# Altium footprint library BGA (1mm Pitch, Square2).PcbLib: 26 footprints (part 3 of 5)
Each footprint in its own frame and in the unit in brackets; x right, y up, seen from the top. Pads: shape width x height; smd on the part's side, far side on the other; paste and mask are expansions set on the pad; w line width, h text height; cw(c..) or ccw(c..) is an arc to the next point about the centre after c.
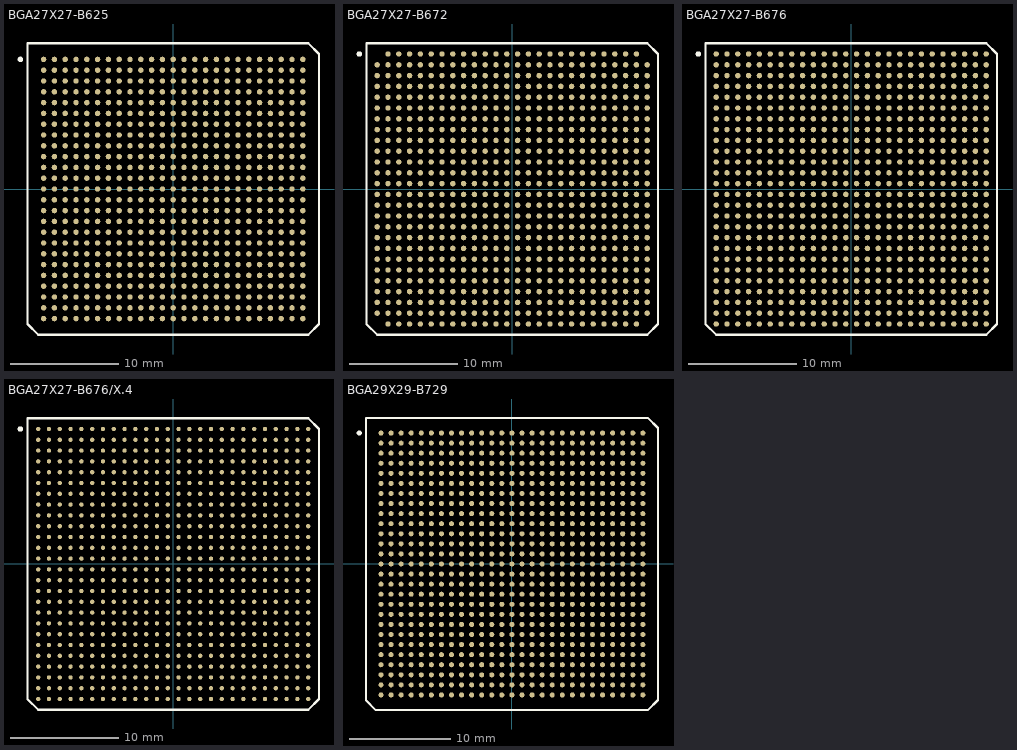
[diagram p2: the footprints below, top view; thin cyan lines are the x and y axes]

## BGA27X27-B625 [mm]
pads (625):
  round 0.5 smd: A1(-12,12) A2(-11,12) A3(-10,12) A4(-9,12) A5(-8,12) A6(-7,12) A7(-6,12) A8(-5,12) A9(-4,12) A10(-3,12) A11(-2,12) A12(-1,12) A13(0,12) A14(1,12) A15(2,12) A16(3,12) A17(4,12) A18(5,12) A19(6,12) A20(7,12) A21(8,12) A22(9,12) A23(10,12) A24(11,12) A25(12,12) AA1(-12,-8) AA2(-11,-8) AA3(-10,-8) AA4(-9,-8) AA5(-8,-8) AA6(-7,-8) AA7(-6,-8) AA8(-5,-8) AA9(-4,-8) AA10(-3,-8) AA11(-2,-8) AA12(-1,-8) AA13(0,-8) AA14(1,-8) AA15(2,-8) AA16(3,-8) AA17(4,-8) AA18(5,-8) AA19(6,-8) AA20(7,-8) AA21(8,-8) AA22(9,-8) AA23(10,-8) AA24(11,-8) AA25(12,-8) AB1(-12,-9) AB2(-11,-9) AB3(-10,-9) AB4(-9,-9) AB5(-8,-9) AB6(-7,-9) AB7(-6,-9) AB8(-5,-9) AB9(-4,-9) AB10(-3,-9) AB11(-2,-9) AB12(-1,-9) AB13(0,-9) AB14(1,-9) AB15(2,-9) AB16(3,-9) AB17(4,-9) AB18(5,-9) AB19(6,-9) AB20(7,-9) AB21(8,-9) AB22(9,-9) AB23(10,-9) AB24(11,-9) AB25(12,-9) AC1(-12,-10) AC2(-11,-10) AC3(-10,-10) AC4(-9,-10) AC5(-8,-10) AC6(-7,-10) AC7(-6,-10) AC8(-5,-10) AC9(-4,-10) AC10(-3,-10) AC11(-2,-10) AC12(-1,-10) AC13(0,-10) AC14(1,-10) AC15(2,-10) AC16(3,-10) AC17(4,-10) AC18(5,-10) AC19(6,-10) AC20(7,-10) AC21(8,-10) AC22(9,-10) AC23(10,-10) AC24(11,-10) AC25(12,-10) AD1(-12,-11) AD2(-11,-11) AD3(-10,-11) AD4(-9,-11) AD5(-8,-11) AD6(-7,-11) AD7(-6,-11) AD8(-5,-11) AD9(-4,-11) AD10(-3,-11) AD11(-2,-11) AD12(-1,-11) AD13(0,-11) AD14(1,-11) AD15(2,-11) AD16(3,-11) AD17(4,-11) AD18(5,-11) AD19(6,-11) AD20(7,-11) AD21(8,-11) AD22(9,-11) AD23(10,-11) AD24(11,-11) AD25(12,-11) AE1(-12,-12) AE2(-11,-12) AE3(-10,-12) AE4(-9,-12) AE5(-8,-12) AE6(-7,-12) AE7(-6,-12) AE8(-5,-12) AE9(-4,-12) AE10(-3,-12) AE11(-2,-12) AE12(-1,-12) AE13(0,-12) AE14(1,-12) AE15(2,-12) AE16(3,-12) AE17(4,-12) AE18(5,-12) AE19(6,-12) AE20(7,-12) AE21(8,-12) AE22(9,-12) AE23(10,-12) AE24(11,-12) AE25(12,-12) B1(-12,11) B2(-11,11) B3(-10,11) B4(-9,11) B5(-8,11) B6(-7,11) B7(-6,11) B8(-5,11) B9(-4,11) B10(-3,11) B11(-2,11) B12(-1,11) B13(0,11) B14(1,11) B15(2,11) B16(3,11) B17(4,11) B18(5,11) B19(6,11) B20(7,11) B21(8,11) B22(9,11) B23(10,11) B24(11,11) B25(12,11) C1(-12,10) C2(-11,10) C3(-10,10) C4(-9,10) C5(-8,10) C6(-7,10) C7(-6,10) C8(-5,10) C9(-4,10) C10(-3,10) C11(-2,10) C12(-1,10) C13(0,10) C14(1,10) C15(2,10) C16(3,10) C17(4,10) C18(5,10) C19(6,10) C20(7,10) C21(8,10) C22(9,10) C23(10,10) C24(11,10) C25(12,10) D1(-12,9) D2(-11,9) D3(-10,9) D4(-9,9) D5(-8,9) D6(-7,9) D7(-6,9) D8(-5,9) D9(-4,9) D10(-3,9) D11(-2,9) D12(-1,9) D13(0,9) D14(1,9) D15(2,9) D16(3,9) D17(4,9) D18(5,9) D19(6,9) D20(7,9) D21(8,9) D22(9,9) D23(10,9) D24(11,9) D25(12,9) E1(-12,8) E2(-11,8) E3(-10,8) E4(-9,8) E5(-8,8) E6(-7,8) E7(-6,8) E8(-5,8) E9(-4,8) E10(-3,8) E11(-2,8) E12(-1,8) E13(0,8) E14(1,8) E15(2,8) E16(3,8) E17(4,8) E18(5,8) E19(6,8) E20(7,8) E21(8,8) E22(9,8) E23(10,8) E24(11,8) E25(12,8) F1(-12,7) F2(-11,7) F3(-10,7) F4(-9,7) F5(-8,7) F6(-7,7) F7(-6,7) F8(-5,7) F9(-4,7) F10(-3,7) F11(-2,7) F12(-1,7) F13(0,7) F14(1,7) F15(2,7) F16(3,7) F17(4,7) F18(5,7) F19(6,7) F20(7,7) F21(8,7) F22(9,7) F23(10,7) F24(11,7) F25(12,7) G1(-12,6) G2(-11,6) G3(-10,6) G4(-9,6) G5(-8,6) G6(-7,6) G7(-6,6) G8(-5,6) G9(-4,6) G10(-3,6) G11(-2,6) G12(-1,6) G13(0,6) G14(1,6) G15(2,6) G16(3,6) G17(4,6) G18(5,6) G19(6,6) G20(7,6) G21(8,6) G22(9,6) G23(10,6) G24(11,6) G25(12,6) H1(-12,5) H2(-11,5) H3(-10,5) H4(-9,5) H5(-8,5) H6(-7,5) H7(-6,5) H8(-5,5) H9(-4,5) H10(-3,5) H11(-2,5) H12(-1,5) H13(0,5) H14(1,5) H15(2,5) H16(3,5) H17(4,5) H18(5,5) H19(6,5) H20(7,5) H21(8,5) H22(9,5) H23(10,5) H24(11,5) H25(12,5) J1(-12,4) J2(-11,4) J3(-10,4) J4(-9,4) J5(-8,4) J6(-7,4) J7(-6,4) J8(-5,4) J9(-4,4) J10(-3,4) J11(-2,4) J12(-1,4) J13(0,4) J14(1,4) J15(2,4) J16(3,4) J17(4,4) J18(5,4) J19(6,4) J20(7,4) J21(8,4) J22(9,4) J23(10,4) J24(11,4) J25(12,4) K1(-12,3) K2(-11,3) K3(-10,3) K4(-9,3) K5(-8,3) K6(-7,3) K7(-6,3) K8(-5,3) K9(-4,3) K10(-3,3) K11(-2,3) K12(-1,3) K13(0,3) K14(1,3) K15(2,3) K16(3,3) K17(4,3) K18(5,3) K19(6,3) K20(7,3) K21(8,3) K22(9,3) K23(10,3) K24(11,3) K25(12,3) L1(-12,2) L2(-11,2) L3(-10,2) L4(-9,2) L5(-8,2) L6(-7,2) L7(-6,2) L8(-5,2) L9(-4,2) L10(-3,2) L11(-2,2) L12(-1,2) L13(0,2) L14(1,2) L15(2,2) L16(3,2) L17(4,2) L18(5,2) L19(6,2) L20(7,2) L21(8,2) L22(9,2) L23(10,2) L24(11,2) L25(12,2) M1(-12,1) M2(-11,1) M3(-10,1) M4(-9,1) M5(-8,1) M6(-7,1) M7(-6,1) M8(-5,1) M9(-4,1) M10(-3,1) M11(-2,1) M12(-1,1) M13(0,1) M14(1,1) M15(2,1) M16(3,1) M17(4,1) M18(5,1) M19(6,1) M20(7,1) M21(8,1) M22(9,1) M23(10,1) M24(11,1) M25(12,1) N1(-12,0) N2(-11,0) N3(-10,0) N4(-9,0) N5(-8,0) N6(-7,0) N7(-6,0) N8(-5,0) N9(-4,0) N10(-3,0) N11(-2,0) N12(-1,0) N13(0,0) N14(1,0) N15(2,0) N16(3,0) N17(4,0) N18(5,0) N19(6,0) N20(7,0) N21(8,0) N22(9,0) N23(10,0) N24(11,0) N25(12,0) P1(-12,-1) P2(-11,-1) P3(-10,-1) P4(-9,-1) P5(-8,-1) P6(-7,-1) P7(-6,-1) P8(-5,-1) P9(-4,-1) P10(-3,-1) P11(-2,-1) P12(-1,-1) P13(0,-1) P14(1,-1) P15(2,-1) P16(3,-1) P17(4,-1) P18(5,-1) P19(6,-1) P20(7,-1) P21(8,-1) P22(9,-1) P23(10,-1) P24(11,-1) P25(12,-1) R1(-12,-2) R2(-11,-2) R3(-10,-2) R4(-9,-2) R5(-8,-2) R6(-7,-2) R7(-6,-2) R8(-5,-2) R9(-4,-2) R10(-3,-2) R11(-2,-2) R12(-1,-2) R13(0,-2) R14(1,-2) R15(2,-2) R16(3,-2) R17(4,-2) R18(5,-2) R19(6,-2) R20(7,-2) R21(8,-2) R22(9,-2) R23(10,-2) R24(11,-2) R25(12,-2) T1(-12,-3) T2(-11,-3) T3(-10,-3) T4(-9,-3) T5(-8,-3) T6(-7,-3) T7(-6,-3) T8(-5,-3) T9(-4,-3) T10(-3,-3) T11(-2,-3) T12(-1,-3) T13(0,-3) T14(1,-3) T15(2,-3) T16(3,-3) T17(4,-3) T18(5,-3) T19(6,-3) T20(7,-3) T21(8,-3) T22(9,-3) T23(10,-3) T24(11,-3) T25(12,-3) U1(-12,-4) U2(-11,-4) U3(-10,-4) U4(-9,-4) U5(-8,-4) U6(-7,-4) U7(-6,-4) U8(-5,-4) U9(-4,-4) U10(-3,-4) U11(-2,-4) U12(-1,-4) U13(0,-4) U14(1,-4) U15(2,-4) U16(3,-4) U17(4,-4) U18(5,-4) U19(6,-4) U20(7,-4) U21(8,-4) U22(9,-4) U23(10,-4) U24(11,-4) U25(12,-4) V1(-12,-5) V2(-11,-5) V3(-10,-5) V4(-9,-5) V5(-8,-5) V6(-7,-5) V7(-6,-5) V8(-5,-5) V9(-4,-5) V10(-3,-5) V11(-2,-5) V12(-1,-5) V13(0,-5) V14(1,-5) V15(2,-5) V16(3,-5) V17(4,-5) V18(5,-5) V19(6,-5) V20(7,-5) V21(8,-5) V22(9,-5) V23(10,-5) V24(11,-5) V25(12,-5) W1(-12,-6) W2(-11,-6) W3(-10,-6) W4(-9,-6) W5(-8,-6) W6(-7,-6) W7(-6,-6) W8(-5,-6) W9(-4,-6) W10(-3,-6) W11(-2,-6) W12(-1,-6) W13(0,-6) W14(1,-6) W15(2,-6) W16(3,-6) W17(4,-6) W18(5,-6) W19(6,-6) W20(7,-6) W21(8,-6) W22(9,-6) W23(10,-6) W24(11,-6) W25(12,-6) Y1(-12,-7) Y2(-11,-7) Y3(-10,-7) Y4(-9,-7) Y5(-8,-7) Y6(-7,-7) Y7(-6,-7) Y8(-5,-7) Y9(-4,-7) Y10(-3,-7) Y11(-2,-7) Y12(-1,-7) Y13(0,-7) Y14(1,-7) Y15(2,-7) Y16(3,-7) Y17(4,-7) Y18(5,-7) Y19(6,-7) Y20(7,-7) Y21(8,-7) Y22(9,-7) Y23(10,-7) Y24(11,-7) Y25(12,-7)
Top Overlay:
  circle w0.25: c-14.155,12 r0.125
  lines w0.2: -13.5,-12.5 -12.5,-13.5 12.5,-13.5 13.5,-12.5 13.5,12.5 12.5,13.5 -13.5,13.5 -13.5,-12.5

## BGA27X27-B672 [mm]
pads (672):
  round 0.5 smd: A2(-11.5,12.5) A3(-10.5,12.5) A4(-9.5,12.5) A5(-8.5,12.5) A6(-7.5,12.5) A7(-6.5,12.5) A8(-5.5,12.5) A9(-4.5,12.5) A10(-3.5,12.5) A11(-2.5,12.5) A12(-1.5,12.5) A13(-0.5,12.5) A14(0.5,12.5) A15(1.5,12.5) A16(2.5,12.5) A17(3.5,12.5) A18(4.5,12.5) A19(5.5,12.5) A20(6.5,12.5) A21(7.5,12.5) A22(8.5,12.5) A23(9.5,12.5) A24(10.5,12.5) A25(11.5,12.5) AA1(-12.5,-7.5) AA2(-11.5,-7.5) AA3(-10.5,-7.5) AA4(-9.5,-7.5) AA5(-8.5,-7.5) AA6(-7.5,-7.5) AA7(-6.5,-7.5) AA8(-5.5,-7.5) AA9(-4.5,-7.5) AA10(-3.5,-7.5) AA11(-2.5,-7.5) AA12(-1.5,-7.5) AA13(-0.5,-7.5) AA14(0.5,-7.5) AA15(1.5,-7.5) AA16(2.5,-7.5) AA17(3.5,-7.5) AA18(4.5,-7.5) AA19(5.5,-7.5) AA20(6.5,-7.5) AA21(7.5,-7.5) AA22(8.5,-7.5) AA23(9.5,-7.5) AA24(10.5,-7.5) AA25(11.5,-7.5) AA26(12.5,-7.5) AB1(-12.5,-8.5) AB2(-11.5,-8.5) AB3(-10.5,-8.5) AB4(-9.5,-8.5) AB5(-8.5,-8.5) AB6(-7.5,-8.5) AB7(-6.5,-8.5) AB8(-5.5,-8.5) AB9(-4.5,-8.5) AB10(-3.5,-8.5) AB11(-2.5,-8.5) AB12(-1.5,-8.5) AB13(-0.5,-8.5) AB14(0.5,-8.5) AB15(1.5,-8.5) AB16(2.5,-8.5) AB17(3.5,-8.5) AB18(4.5,-8.5) AB19(5.5,-8.5) AB20(6.5,-8.5) AB21(7.5,-8.5) AB22(8.5,-8.5) AB23(9.5,-8.5) AB24(10.5,-8.5) AB25(11.5,-8.5) AB26(12.5,-8.5) AC1(-12.5,-9.5) AC2(-11.5,-9.5) AC3(-10.5,-9.5) AC4(-9.5,-9.5) AC5(-8.5,-9.5) AC6(-7.5,-9.5) AC7(-6.5,-9.5) AC8(-5.5,-9.5) AC9(-4.5,-9.5) AC10(-3.5,-9.5) AC11(-2.5,-9.5) AC12(-1.5,-9.5) AC13(-0.5,-9.5) AC14(0.5,-9.5) AC15(1.5,-9.5) AC16(2.5,-9.5) AC17(3.5,-9.5) AC18(4.5,-9.5) AC19(5.5,-9.5) AC20(6.5,-9.5) AC21(7.5,-9.5) AC22(8.5,-9.5) AC23(9.5,-9.5) AC24(10.5,-9.5) AC25(11.5,-9.5) AC26(12.5,-9.5) AD1(-12.5,-10.5) AD2(-11.5,-10.5) AD3(-10.5,-10.5) AD4(-9.5,-10.5) AD5(-8.5,-10.5) AD6(-7.5,-10.5) AD7(-6.5,-10.5) AD8(-5.5,-10.5) AD9(-4.5,-10.5) AD10(-3.5,-10.5) AD11(-2.5,-10.5) AD12(-1.5,-10.5) AD13(-0.5,-10.5) AD14(0.5,-10.5) AD15(1.5,-10.5) AD16(2.5,-10.5) AD17(3.5,-10.5) AD18(4.5,-10.5) AD19(5.5,-10.5) AD20(6.5,-10.5) AD21(7.5,-10.5) AD22(8.5,-10.5) AD23(9.5,-10.5) AD24(10.5,-10.5) AD25(11.5,-10.5) AD26(12.5,-10.5) AE1(-12.5,-11.5) AE2(-11.5,-11.5) AE3(-10.5,-11.5) AE4(-9.5,-11.5) AE5(-8.5,-11.5) AE6(-7.5,-11.5) AE7(-6.5,-11.5) AE8(-5.5,-11.5) AE9(-4.5,-11.5) AE10(-3.5,-11.5) AE11(-2.5,-11.5) AE12(-1.5,-11.5) AE13(-0.5,-11.5) AE14(0.5,-11.5) AE15(1.5,-11.5) AE16(2.5,-11.5) AE17(3.5,-11.5) AE18(4.5,-11.5) AE19(5.5,-11.5) AE20(6.5,-11.5) AE21(7.5,-11.5) AE22(8.5,-11.5) AE23(9.5,-11.5) AE24(10.5,-11.5) AE25(11.5,-11.5) AE26(12.5,-11.5) AF2(-11.5,-12.5) AF3(-10.5,-12.5) AF4(-9.5,-12.5) AF5(-8.5,-12.5) AF6(-7.5,-12.5) AF7(-6.5,-12.5) AF8(-5.5,-12.5) AF9(-4.5,-12.5) AF10(-3.5,-12.5) AF11(-2.5,-12.5) AF12(-1.5,-12.5) AF13(-0.5,-12.5) AF14(0.5,-12.5) AF15(1.5,-12.5) AF16(2.5,-12.5) AF17(3.5,-12.5) AF18(4.5,-12.5) AF19(5.5,-12.5) AF20(6.5,-12.5) AF21(7.5,-12.5) AF22(8.5,-12.5) AF23(9.5,-12.5) AF24(10.5,-12.5) AF25(11.5,-12.5) B1(-12.5,11.5) B2(-11.5,11.5) B3(-10.5,11.5) B4(-9.5,11.5) B5(-8.5,11.5) B6(-7.5,11.5) B7(-6.5,11.5) B8(-5.5,11.5) B9(-4.5,11.5) B10(-3.5,11.5) B11(-2.5,11.5) B12(-1.5,11.5) B13(-0.5,11.5) B14(0.5,11.5) B15(1.5,11.5) B16(2.5,11.5) B17(3.5,11.5) B18(4.5,11.5) B19(5.5,11.5) B20(6.5,11.5) B21(7.5,11.5) B22(8.5,11.5) B23(9.5,11.5) B24(10.5,11.5) B25(11.5,11.5) B26(12.5,11.5) C1(-12.5,10.5) C2(-11.5,10.5) C3(-10.5,10.5) C4(-9.5,10.5) C5(-8.5,10.5) C6(-7.5,10.5) C7(-6.5,10.5) C8(-5.5,10.5) C9(-4.5,10.5) C10(-3.5,10.5) C11(-2.5,10.5) C12(-1.5,10.5) C13(-0.5,10.5) C14(0.5,10.5) C15(1.5,10.5) C16(2.5,10.5) C17(3.5,10.5) C18(4.5,10.5) C19(5.5,10.5) C20(6.5,10.5) C21(7.5,10.5) C22(8.5,10.5) C23(9.5,10.5) C24(10.5,10.5) C25(11.5,10.5) C26(12.5,10.5) D1(-12.5,9.5) D2(-11.5,9.5) D3(-10.5,9.5) D4(-9.5,9.5) D5(-8.5,9.5) D6(-7.5,9.5) D7(-6.5,9.5) D8(-5.5,9.5) D9(-4.5,9.5) D10(-3.5,9.5) D11(-2.5,9.5) D12(-1.5,9.5) D13(-0.5,9.5) D14(0.5,9.5) D15(1.5,9.5) D16(2.5,9.5) D17(3.5,9.5) D18(4.5,9.5) D19(5.5,9.5) D20(6.5,9.5) D21(7.5,9.5) D22(8.5,9.5) D23(9.5,9.5) D24(10.5,9.5) D25(11.5,9.5) D26(12.5,9.5) E1(-12.5,8.5) E2(-11.5,8.5) E3(-10.5,8.5) E4(-9.5,8.5) E5(-8.5,8.5) E6(-7.5,8.5) E7(-6.5,8.5) E8(-5.5,8.5) E9(-4.5,8.5) E10(-3.5,8.5) E11(-2.5,8.5) E12(-1.5,8.5) E13(-0.5,8.5) E14(0.5,8.5) E15(1.5,8.5) E16(2.5,8.5) E17(3.5,8.5) E18(4.5,8.5) E19(5.5,8.5) E20(6.5,8.5) E21(7.5,8.5) E22(8.5,8.5) E23(9.5,8.5) E24(10.5,8.5) E25(11.5,8.5) E26(12.5,8.5) F1(-12.5,7.5) F2(-11.5,7.5) F3(-10.5,7.5) F4(-9.5,7.5) F5(-8.5,7.5) F6(-7.5,7.5) F7(-6.5,7.5) F8(-5.5,7.5) F9(-4.5,7.5) F10(-3.5,7.5) F11(-2.5,7.5) F12(-1.5,7.5) F13(-0.5,7.5) F14(0.5,7.5) F15(1.5,7.5) F16(2.5,7.5) F17(3.5,7.5) F18(4.5,7.5) F19(5.5,7.5) F20(6.5,7.5) F21(7.5,7.5) F22(8.5,7.5) F23(9.5,7.5) F24(10.5,7.5) F25(11.5,7.5) F26(12.5,7.5) G1(-12.5,6.5) G2(-11.5,6.5) G3(-10.5,6.5) G4(-9.5,6.5) G5(-8.5,6.5) G6(-7.5,6.5) G7(-6.5,6.5) G8(-5.5,6.5) G9(-4.5,6.5) G10(-3.5,6.5) G11(-2.5,6.5) G12(-1.5,6.5) G13(-0.5,6.5) G14(0.5,6.5) G15(1.5,6.5) G16(2.5,6.5) G17(3.5,6.5) G18(4.5,6.5) G19(5.5,6.5) G20(6.5,6.5) G21(7.5,6.5) G22(8.5,6.5) G23(9.5,6.5) G24(10.5,6.5) G25(11.5,6.5) G26(12.5,6.5) H1(-12.5,5.5) H2(-11.5,5.5) H3(-10.5,5.5) H4(-9.5,5.5) H5(-8.5,5.5) H6(-7.5,5.5) H7(-6.5,5.5) H8(-5.5,5.5) H9(-4.5,5.5) H10(-3.5,5.5) H11(-2.5,5.5) H12(-1.5,5.5) H13(-0.5,5.5) H14(0.5,5.5) H15(1.5,5.5) H16(2.5,5.5) H17(3.5,5.5) H18(4.5,5.5) H19(5.5,5.5) H20(6.5,5.5) H21(7.5,5.5) H22(8.5,5.5) H23(9.5,5.5) H24(10.5,5.5) H25(11.5,5.5) H26(12.5,5.5) J1(-12.5,4.5) J2(-11.5,4.5) J3(-10.5,4.5) J4(-9.5,4.5) J5(-8.5,4.5) J6(-7.5,4.5) J7(-6.5,4.5) J8(-5.5,4.5) J9(-4.5,4.5) J10(-3.5,4.5) J11(-2.5,4.5) J12(-1.5,4.5) J13(-0.5,4.5) J14(0.5,4.5) J15(1.5,4.5) J16(2.5,4.5) J17(3.5,4.5) J18(4.5,4.5) J19(5.5,4.5) J20(6.5,4.5) J21(7.5,4.5) J22(8.5,4.5) J23(9.5,4.5) J24(10.5,4.5) J25(11.5,4.5) J26(12.5,4.5) K1(-12.5,3.5) K2(-11.5,3.5) K3(-10.5,3.5) K4(-9.5,3.5) K5(-8.5,3.5) K6(-7.5,3.5) K7(-6.5,3.5) K8(-5.5,3.5) K9(-4.5,3.5) K10(-3.5,3.5) K11(-2.5,3.5) K12(-1.5,3.5) K13(-0.5,3.5) K14(0.5,3.5) K15(1.5,3.5) K16(2.5,3.5) K17(3.5,3.5) K18(4.5,3.5) K19(5.5,3.5) K20(6.5,3.5) K21(7.5,3.5) K22(8.5,3.5) K23(9.5,3.5) K24(10.5,3.5) K25(11.5,3.5) K26(12.5,3.5) L1(-12.5,2.5) L2(-11.5,2.5) L3(-10.5,2.5) L4(-9.5,2.5) L5(-8.5,2.5) L6(-7.5,2.5) L7(-6.5,2.5) L8(-5.5,2.5) L9(-4.5,2.5) L10(-3.5,2.5) L11(-2.5,2.5) L12(-1.5,2.5) L13(-0.5,2.5) L14(0.5,2.5) L15(1.5,2.5) L16(2.5,2.5) L17(3.5,2.5) L18(4.5,2.5) L19(5.5,2.5) L20(6.5,2.5) L21(7.5,2.5) L22(8.5,2.5) L23(9.5,2.5) L24(10.5,2.5) L25(11.5,2.5) L26(12.5,2.5) M1(-12.5,1.5) M2(-11.5,1.5) M3(-10.5,1.5) M4(-9.5,1.5) M5(-8.5,1.5) M6(-7.5,1.5) M7(-6.5,1.5) M8(-5.5,1.5) M9(-4.5,1.5) M10(-3.5,1.5) M11(-2.5,1.5) M12(-1.5,1.5) M13(-0.5,1.5) M14(0.5,1.5) M15(1.5,1.5) M16(2.5,1.5) M17(3.5,1.5) M18(4.5,1.5) M19(5.5,1.5) M20(6.5,1.5) M21(7.5,1.5) M22(8.5,1.5) M23(9.5,1.5) M24(10.5,1.5) M25(11.5,1.5) M26(12.5,1.5) N1(-12.5,0.5) N2(-11.5,0.5) N3(-10.5,0.5) N4(-9.5,0.5) N5(-8.5,0.5) N6(-7.5,0.5) N7(-6.5,0.5) N8(-5.5,0.5) N9(-4.5,0.5) N10(-3.5,0.5) N11(-2.5,0.5) N12(-1.5,0.5) N13(-0.5,0.5) N14(0.5,0.5) N15(1.5,0.5) N16(2.5,0.5) N17(3.5,0.5) N18(4.5,0.5) N19(5.5,0.5) N20(6.5,0.5) N21(7.5,0.5) N22(8.5,0.5) N23(9.5,0.5) N24(10.5,0.5) N25(11.5,0.5) N26(12.5,0.5) P1(-12.5,-0.5) P2(-11.5,-0.5) P3(-10.5,-0.5) P4(-9.5,-0.5) P5(-8.5,-0.5) P6(-7.5,-0.5) P7(-6.5,-0.5) P8(-5.5,-0.5) P9(-4.5,-0.5) P10(-3.5,-0.5) P11(-2.5,-0.5) P12(-1.5,-0.5) P13(-0.5,-0.5) P14(0.5,-0.5) P15(1.5,-0.5) P16(2.5,-0.5) P17(3.5,-0.5) P18(4.5,-0.5) P19(5.5,-0.5) P20(6.5,-0.5) P21(7.5,-0.5) P22(8.5,-0.5) P23(9.5,-0.5) P24(10.5,-0.5) P25(11.5,-0.5) P26(12.5,-0.5) R1(-12.5,-1.5) R2(-11.5,-1.5) R3(-10.5,-1.5) R4(-9.5,-1.5) R5(-8.5,-1.5) R6(-7.5,-1.5) R7(-6.5,-1.5) R8(-5.5,-1.5) R9(-4.5,-1.5) R10(-3.5,-1.5) R11(-2.5,-1.5) R12(-1.5,-1.5) R13(-0.5,-1.5) R14(0.5,-1.5) R15(1.5,-1.5) R16(2.5,-1.5) R17(3.5,-1.5) R18(4.5,-1.5) R19(5.5,-1.5) R20(6.5,-1.5) R21(7.5,-1.5) R22(8.5,-1.5) R23(9.5,-1.5) R24(10.5,-1.5) R25(11.5,-1.5) R26(12.5,-1.5) T1(-12.5,-2.5) T2(-11.5,-2.5) T3(-10.5,-2.5) T4(-9.5,-2.5) T5(-8.5,-2.5) T6(-7.5,-2.5) T7(-6.5,-2.5) T8(-5.5,-2.5) T9(-4.5,-2.5) T10(-3.5,-2.5) T11(-2.5,-2.5) T12(-1.5,-2.5) T13(-0.5,-2.5) T14(0.5,-2.5) T15(1.5,-2.5) T16(2.5,-2.5) T17(3.5,-2.5) T18(4.5,-2.5) T19(5.5,-2.5) T20(6.5,-2.5) T21(7.5,-2.5) T22(8.5,-2.5) T23(9.5,-2.5) T24(10.5,-2.5) T25(11.5,-2.5) T26(12.5,-2.5) U1(-12.5,-3.5) U2(-11.5,-3.5) U3(-10.5,-3.5) U4(-9.5,-3.5) U5(-8.5,-3.5) U6(-7.5,-3.5) U7(-6.5,-3.5) U8(-5.5,-3.5) U9(-4.5,-3.5) U10(-3.5,-3.5) U11(-2.5,-3.5) U12(-1.5,-3.5) U13(-0.5,-3.5) U14(0.5,-3.5) U15(1.5,-3.5) U16(2.5,-3.5) U17(3.5,-3.5) U18(4.5,-3.5) U19(5.5,-3.5) U20(6.5,-3.5) U21(7.5,-3.5) U22(8.5,-3.5) U23(9.5,-3.5) U24(10.5,-3.5) U25(11.5,-3.5) U26(12.5,-3.5) V1(-12.5,-4.5) V2(-11.5,-4.5) V3(-10.5,-4.5) V4(-9.5,-4.5) V5(-8.5,-4.5) V6(-7.5,-4.5) V7(-6.5,-4.5) V8(-5.5,-4.5) V9(-4.5,-4.5) V10(-3.5,-4.5) V11(-2.5,-4.5) V12(-1.5,-4.5) V13(-0.5,-4.5) V14(0.5,-4.5) V15(1.5,-4.5) V16(2.5,-4.5) V17(3.5,-4.5) V18(4.5,-4.5) V19(5.5,-4.5) V20(6.5,-4.5) V21(7.5,-4.5) V22(8.5,-4.5) V23(9.5,-4.5) V24(10.5,-4.5) V25(11.5,-4.5) V26(12.5,-4.5) W1(-12.5,-5.5) W2(-11.5,-5.5) W3(-10.5,-5.5) W4(-9.5,-5.5) W5(-8.5,-5.5) W6(-7.5,-5.5) W7(-6.5,-5.5) W8(-5.5,-5.5) W9(-4.5,-5.5) W10(-3.5,-5.5) W11(-2.5,-5.5) W12(-1.5,-5.5) W13(-0.5,-5.5) W14(0.5,-5.5) W15(1.5,-5.5) W16(2.5,-5.5) W17(3.5,-5.5) W18(4.5,-5.5) W19(5.5,-5.5) W20(6.5,-5.5) W21(7.5,-5.5) W22(8.5,-5.5) W23(9.5,-5.5) W24(10.5,-5.5) W25(11.5,-5.5) W26(12.5,-5.5) Y1(-12.5,-6.5) Y2(-11.5,-6.5) Y3(-10.5,-6.5) Y4(-9.5,-6.5) Y5(-8.5,-6.5) Y6(-7.5,-6.5) Y7(-6.5,-6.5) Y8(-5.5,-6.5) Y9(-4.5,-6.5) Y10(-3.5,-6.5) Y11(-2.5,-6.5) Y12(-1.5,-6.5) Y13(-0.5,-6.5) Y14(0.5,-6.5) Y15(1.5,-6.5) Y16(2.5,-6.5) Y17(3.5,-6.5) Y18(4.5,-6.5) Y19(5.5,-6.5) Y20(6.5,-6.5) Y21(7.5,-6.5) Y22(8.5,-6.5) Y23(9.5,-6.5) Y24(10.5,-6.5) Y25(11.5,-6.5) Y26(12.5,-6.5)
Top Overlay:
  circle w0.25: c-14.15,12.5 r0.125
  lines w0.2: -13.5,-12.5 -12.5,-13.5 12.5,-13.5 13.5,-12.5 13.5,12.5 12.5,13.5 -13.5,13.5 -13.5,-12.5

## BGA27X27-B676 [mm]
pads (676):
  round 0.5 smd: A1(-12.5,12.5) A2(-11.5,12.5) A3(-10.5,12.5) A4(-9.5,12.5) A5(-8.5,12.5) A6(-7.5,12.5) A7(-6.5,12.5) A8(-5.5,12.5) A9(-4.5,12.5) A10(-3.5,12.5) A11(-2.5,12.5) A12(-1.5,12.5) A13(-0.5,12.5) A14(0.5,12.5) A15(1.5,12.5) A16(2.5,12.5) A17(3.5,12.5) A18(4.5,12.5) A19(5.5,12.5) A20(6.5,12.5) A21(7.5,12.5) A22(8.5,12.5) A23(9.5,12.5) A24(10.5,12.5) A25(11.5,12.5) A26(12.5,12.5) AA1(-12.5,-7.5) AA2(-11.5,-7.5) AA3(-10.5,-7.5) AA4(-9.5,-7.5) AA5(-8.5,-7.5) AA6(-7.5,-7.5) AA7(-6.5,-7.5) AA8(-5.5,-7.5) AA9(-4.5,-7.5) AA10(-3.5,-7.5) AA11(-2.5,-7.5) AA12(-1.5,-7.5) AA13(-0.5,-7.5) AA14(0.5,-7.5) AA15(1.5,-7.5) AA16(2.5,-7.5) AA17(3.5,-7.5) AA18(4.5,-7.5) AA19(5.5,-7.5) AA20(6.5,-7.5) AA21(7.5,-7.5) AA22(8.5,-7.5) AA23(9.5,-7.5) AA24(10.5,-7.5) AA25(11.5,-7.5) AA26(12.5,-7.5) AB1(-12.5,-8.5) AB2(-11.5,-8.5) AB3(-10.5,-8.5) AB4(-9.5,-8.5) AB5(-8.5,-8.5) AB6(-7.5,-8.5) AB7(-6.5,-8.5) AB8(-5.5,-8.5) AB9(-4.5,-8.5) AB10(-3.5,-8.5) AB11(-2.5,-8.5) AB12(-1.5,-8.5) AB13(-0.5,-8.5) AB14(0.5,-8.5) AB15(1.5,-8.5) AB16(2.5,-8.5) AB17(3.5,-8.5) AB18(4.5,-8.5) AB19(5.5,-8.5) AB20(6.5,-8.5) AB21(7.5,-8.5) AB22(8.5,-8.5) AB23(9.5,-8.5) AB24(10.5,-8.5) AB25(11.5,-8.5) AB26(12.5,-8.5) AC1(-12.5,-9.5) AC2(-11.5,-9.5) AC3(-10.5,-9.5) AC4(-9.5,-9.5) AC5(-8.5,-9.5) AC6(-7.5,-9.5) AC7(-6.5,-9.5) AC8(-5.5,-9.5) AC9(-4.5,-9.5) AC10(-3.5,-9.5) AC11(-2.5,-9.5) AC12(-1.5,-9.5) AC13(-0.5,-9.5) AC14(0.5,-9.5) AC15(1.5,-9.5) AC16(2.5,-9.5) AC17(3.5,-9.5) AC18(4.5,-9.5) AC19(5.5,-9.5) AC20(6.5,-9.5) AC21(7.5,-9.5) AC22(8.5,-9.5) AC23(9.5,-9.5) AC24(10.5,-9.5) AC25(11.5,-9.5) AC26(12.5,-9.5) AD1(-12.5,-10.5) AD2(-11.5,-10.5) AD3(-10.5,-10.5) AD4(-9.5,-10.5) AD5(-8.5,-10.5) AD6(-7.5,-10.5) AD7(-6.5,-10.5) AD8(-5.5,-10.5) AD9(-4.5,-10.5) AD10(-3.5,-10.5) AD11(-2.5,-10.5) AD12(-1.5,-10.5) AD13(-0.5,-10.5) AD14(0.5,-10.5) AD15(1.5,-10.5) AD16(2.5,-10.5) AD17(3.5,-10.5) AD18(4.5,-10.5) AD19(5.5,-10.5) AD20(6.5,-10.5) AD21(7.5,-10.5) AD22(8.5,-10.5) AD23(9.5,-10.5) AD24(10.5,-10.5) AD25(11.5,-10.5) AD26(12.5,-10.5) AE1(-12.5,-11.5) AE2(-11.5,-11.5) AE3(-10.5,-11.5) AE4(-9.5,-11.5) AE5(-8.5,-11.5) AE6(-7.5,-11.5) AE7(-6.5,-11.5) AE8(-5.5,-11.5) AE9(-4.5,-11.5) AE10(-3.5,-11.5) AE11(-2.5,-11.5) AE12(-1.5,-11.5) AE13(-0.5,-11.5) AE14(0.5,-11.5) AE15(1.5,-11.5) AE16(2.5,-11.5) AE17(3.5,-11.5) AE18(4.5,-11.5) AE19(5.5,-11.5) AE20(6.5,-11.5) AE21(7.5,-11.5) AE22(8.5,-11.5) AE23(9.5,-11.5) AE24(10.5,-11.5) AE25(11.5,-11.5) AE26(12.5,-11.5) AF1(-12.5,-12.5) AF2(-11.5,-12.5) AF3(-10.5,-12.5) AF4(-9.5,-12.5) AF5(-8.5,-12.5) AF6(-7.5,-12.5) AF7(-6.5,-12.5) AF8(-5.5,-12.5) AF9(-4.5,-12.5) AF10(-3.5,-12.5) AF11(-2.5,-12.5) AF12(-1.5,-12.5) AF13(-0.5,-12.5) AF14(0.5,-12.5) AF15(1.5,-12.5) AF16(2.5,-12.5) AF17(3.5,-12.5) AF18(4.5,-12.5) AF19(5.5,-12.5) AF20(6.5,-12.5) AF21(7.5,-12.5) AF22(8.5,-12.5) AF23(9.5,-12.5) AF24(10.5,-12.5) AF25(11.5,-12.5) AF26(12.5,-12.5) B1(-12.5,11.5) B2(-11.5,11.5) B3(-10.5,11.5) B4(-9.5,11.5) B5(-8.5,11.5) B6(-7.5,11.5) B7(-6.5,11.5) B8(-5.5,11.5) B9(-4.5,11.5) B10(-3.5,11.5) B11(-2.5,11.5) B12(-1.5,11.5) B13(-0.5,11.5) B14(0.5,11.5) B15(1.5,11.5) B16(2.5,11.5) B17(3.5,11.5) B18(4.5,11.5) B19(5.5,11.5) B20(6.5,11.5) B21(7.5,11.5) B22(8.5,11.5) B23(9.5,11.5) B24(10.5,11.5) B25(11.5,11.5) B26(12.5,11.5) C1(-12.5,10.5) C2(-11.5,10.5) C3(-10.5,10.5) C4(-9.5,10.5) C5(-8.5,10.5) C6(-7.5,10.5) C7(-6.5,10.5) C8(-5.5,10.5) C9(-4.5,10.5) C10(-3.5,10.5) C11(-2.5,10.5) C12(-1.5,10.5) C13(-0.5,10.5) C14(0.5,10.5) C15(1.5,10.5) C16(2.5,10.5) C17(3.5,10.5) C18(4.5,10.5) C19(5.5,10.5) C20(6.5,10.5) C21(7.5,10.5) C22(8.5,10.5) C23(9.5,10.5) C24(10.5,10.5) C25(11.5,10.5) C26(12.5,10.5) D1(-12.5,9.5) D2(-11.5,9.5) D3(-10.5,9.5) D4(-9.5,9.5) D5(-8.5,9.5) D6(-7.5,9.5) D7(-6.5,9.5) D8(-5.5,9.5) D9(-4.5,9.5) D10(-3.5,9.5) D11(-2.5,9.5) D12(-1.5,9.5) D13(-0.5,9.5) D14(0.5,9.5) D15(1.5,9.5) D16(2.5,9.5) D17(3.5,9.5) D18(4.5,9.5) D19(5.5,9.5) D20(6.5,9.5) D21(7.5,9.5) D22(8.5,9.5) D23(9.5,9.5) D24(10.5,9.5) D25(11.5,9.5) D26(12.5,9.5) E1(-12.5,8.5) E2(-11.5,8.5) E3(-10.5,8.5) E4(-9.5,8.5) E5(-8.5,8.5) E6(-7.5,8.5) E7(-6.5,8.5) E8(-5.5,8.5) E9(-4.5,8.5) E10(-3.5,8.5) E11(-2.5,8.5) E12(-1.5,8.5) E13(-0.5,8.5) E14(0.5,8.5) E15(1.5,8.5) E16(2.5,8.5) E17(3.5,8.5) E18(4.5,8.5) E19(5.5,8.5) E20(6.5,8.5) E21(7.5,8.5) E22(8.5,8.5) E23(9.5,8.5) E24(10.5,8.5) E25(11.5,8.5) E26(12.5,8.5) F1(-12.5,7.5) F2(-11.5,7.5) F3(-10.5,7.5) F4(-9.5,7.5) F5(-8.5,7.5) F6(-7.5,7.5) F7(-6.5,7.5) F8(-5.5,7.5) F9(-4.5,7.5) F10(-3.5,7.5) F11(-2.5,7.5) F12(-1.5,7.5) F13(-0.5,7.5) F14(0.5,7.5) F15(1.5,7.5) F16(2.5,7.5) F17(3.5,7.5) F18(4.5,7.5) F19(5.5,7.5) F20(6.5,7.5) F21(7.5,7.5) F22(8.5,7.5) F23(9.5,7.5) F24(10.5,7.5) F25(11.5,7.5) F26(12.5,7.5) G1(-12.5,6.5) G2(-11.5,6.5) G3(-10.5,6.5) G4(-9.5,6.5) G5(-8.5,6.5) G6(-7.5,6.5) G7(-6.5,6.5) G8(-5.5,6.5) G9(-4.5,6.5) G10(-3.5,6.5) G11(-2.5,6.5) G12(-1.5,6.5) G13(-0.5,6.5) G14(0.5,6.5) G15(1.5,6.5) G16(2.5,6.5) G17(3.5,6.5) G18(4.5,6.5) G19(5.5,6.5) G20(6.5,6.5) G21(7.5,6.5) G22(8.5,6.5) G23(9.5,6.5) G24(10.5,6.5) G25(11.5,6.5) G26(12.5,6.5) H1(-12.5,5.5) H2(-11.5,5.5) H3(-10.5,5.5) H4(-9.5,5.5) H5(-8.5,5.5) H6(-7.5,5.5) H7(-6.5,5.5) H8(-5.5,5.5) H9(-4.5,5.5) H10(-3.5,5.5) H11(-2.5,5.5) H12(-1.5,5.5) H13(-0.5,5.5) H14(0.5,5.5) H15(1.5,5.5) H16(2.5,5.5) H17(3.5,5.5) H18(4.5,5.5) H19(5.5,5.5) H20(6.5,5.5) H21(7.5,5.5) H22(8.5,5.5) H23(9.5,5.5) H24(10.5,5.5) H25(11.5,5.5) H26(12.5,5.5) J1(-12.5,4.5) J2(-11.5,4.5) J3(-10.5,4.5) J4(-9.5,4.5) J5(-8.5,4.5) J6(-7.5,4.5) J7(-6.5,4.5) J8(-5.5,4.5) J9(-4.5,4.5) J10(-3.5,4.5) J11(-2.5,4.5) J12(-1.5,4.5) J13(-0.5,4.5) J14(0.5,4.5) J15(1.5,4.5) J16(2.5,4.5) J17(3.5,4.5) J18(4.5,4.5) J19(5.5,4.5) J20(6.5,4.5) J21(7.5,4.5) J22(8.5,4.5) J23(9.5,4.5) J24(10.5,4.5) J25(11.5,4.5) J26(12.5,4.5) K1(-12.5,3.5) K2(-11.5,3.5) K3(-10.5,3.5) K4(-9.5,3.5) K5(-8.5,3.5) K6(-7.5,3.5) K7(-6.5,3.5) K8(-5.5,3.5) K9(-4.5,3.5) K10(-3.5,3.5) K11(-2.5,3.5) K12(-1.5,3.5) K13(-0.5,3.5) K14(0.5,3.5) K15(1.5,3.5) K16(2.5,3.5) K17(3.5,3.5) K18(4.5,3.5) K19(5.5,3.5) K20(6.5,3.5) K21(7.5,3.5) K22(8.5,3.5) K23(9.5,3.5) K24(10.5,3.5) K25(11.5,3.5) K26(12.5,3.5) L1(-12.5,2.5) L2(-11.5,2.5) L3(-10.5,2.5) L4(-9.5,2.5) L5(-8.5,2.5) L6(-7.5,2.5) L7(-6.5,2.5) L8(-5.5,2.5) L9(-4.5,2.5) L10(-3.5,2.5) L11(-2.5,2.5) L12(-1.5,2.5) L13(-0.5,2.5) L14(0.5,2.5) L15(1.5,2.5) L16(2.5,2.5) L17(3.5,2.5) L18(4.5,2.5) L19(5.5,2.5) L20(6.5,2.5) L21(7.5,2.5) L22(8.5,2.5) L23(9.5,2.5) L24(10.5,2.5) L25(11.5,2.5) L26(12.5,2.5) M1(-12.5,1.5) M2(-11.5,1.5) M3(-10.5,1.5) M4(-9.5,1.5) M5(-8.5,1.5) M6(-7.5,1.5) M7(-6.5,1.5) M8(-5.5,1.5) M9(-4.5,1.5) M10(-3.5,1.5) M11(-2.5,1.5) M12(-1.5,1.5) M13(-0.5,1.5) M14(0.5,1.5) M15(1.5,1.5) M16(2.5,1.5) M17(3.5,1.5) M18(4.5,1.5) M19(5.5,1.5) M20(6.5,1.5) M21(7.5,1.5) M22(8.5,1.5) M23(9.5,1.5) M24(10.5,1.5) M25(11.5,1.5) M26(12.5,1.5) N1(-12.5,0.5) N2(-11.5,0.5) N3(-10.5,0.5) N4(-9.5,0.5) N5(-8.5,0.5) N6(-7.5,0.5) N7(-6.5,0.5) N8(-5.5,0.5) N9(-4.5,0.5) N10(-3.5,0.5) N11(-2.5,0.5) N12(-1.5,0.5) N13(-0.5,0.5) N14(0.5,0.5) N15(1.5,0.5) N16(2.5,0.5) N17(3.5,0.5) N18(4.5,0.5) N19(5.5,0.5) N20(6.5,0.5) N21(7.5,0.5) N22(8.5,0.5) N23(9.5,0.5) N24(10.5,0.5) N25(11.5,0.5) N26(12.5,0.5) P1(-12.5,-0.5) P2(-11.5,-0.5) P3(-10.5,-0.5) P4(-9.5,-0.5) P5(-8.5,-0.5) P6(-7.5,-0.5) P7(-6.5,-0.5) P8(-5.5,-0.5) P9(-4.5,-0.5) P10(-3.5,-0.5) P11(-2.5,-0.5) P12(-1.5,-0.5) P13(-0.5,-0.5) P14(0.5,-0.5) P15(1.5,-0.5) P16(2.5,-0.5) P17(3.5,-0.5) P18(4.5,-0.5) P19(5.5,-0.5) P20(6.5,-0.5) P21(7.5,-0.5) P22(8.5,-0.5) P23(9.5,-0.5) P24(10.5,-0.5) P25(11.5,-0.5) P26(12.5,-0.5) R1(-12.5,-1.5) R2(-11.5,-1.5) R3(-10.5,-1.5) R4(-9.5,-1.5) R5(-8.5,-1.5) R6(-7.5,-1.5) R7(-6.5,-1.5) R8(-5.5,-1.5) R9(-4.5,-1.5) R10(-3.5,-1.5) R11(-2.5,-1.5) R12(-1.5,-1.5) R13(-0.5,-1.5) R14(0.5,-1.5) R15(1.5,-1.5) R16(2.5,-1.5) R17(3.5,-1.5) R18(4.5,-1.5) R19(5.5,-1.5) R20(6.5,-1.5) R21(7.5,-1.5) R22(8.5,-1.5) R23(9.5,-1.5) R24(10.5,-1.5) R25(11.5,-1.5) R26(12.5,-1.5) T1(-12.5,-2.5) T2(-11.5,-2.5) T3(-10.5,-2.5) T4(-9.5,-2.5) T5(-8.5,-2.5) T6(-7.5,-2.5) T7(-6.5,-2.5) T8(-5.5,-2.5) T9(-4.5,-2.5) T10(-3.5,-2.5) T11(-2.5,-2.5) T12(-1.5,-2.5) T13(-0.5,-2.5) T14(0.5,-2.5) T15(1.5,-2.5) T16(2.5,-2.5) T17(3.5,-2.5) T18(4.5,-2.5) T19(5.5,-2.5) T20(6.5,-2.5) T21(7.5,-2.5) T22(8.5,-2.5) T23(9.5,-2.5) T24(10.5,-2.5) T25(11.5,-2.5) T26(12.5,-2.5) U1(-12.5,-3.5) U2(-11.5,-3.5) U3(-10.5,-3.5) U4(-9.5,-3.5) U5(-8.5,-3.5) U6(-7.5,-3.5) U7(-6.5,-3.5) U8(-5.5,-3.5) U9(-4.5,-3.5) U10(-3.5,-3.5) U11(-2.5,-3.5) U12(-1.5,-3.5) U13(-0.5,-3.5) U14(0.5,-3.5) U15(1.5,-3.5) U16(2.5,-3.5) U17(3.5,-3.5) U18(4.5,-3.5) U19(5.5,-3.5) U20(6.5,-3.5) U21(7.5,-3.5) U22(8.5,-3.5) U23(9.5,-3.5) U24(10.5,-3.5) U25(11.5,-3.5) U26(12.5,-3.5) V1(-12.5,-4.5) V2(-11.5,-4.5) V3(-10.5,-4.5) V4(-9.5,-4.5) V5(-8.5,-4.5) V6(-7.5,-4.5) V7(-6.5,-4.5) V8(-5.5,-4.5) V9(-4.5,-4.5) V10(-3.5,-4.5) V11(-2.5,-4.5) V12(-1.5,-4.5) V13(-0.5,-4.5) V14(0.5,-4.5) V15(1.5,-4.5) V16(2.5,-4.5) V17(3.5,-4.5) V18(4.5,-4.5) V19(5.5,-4.5) V20(6.5,-4.5) V21(7.5,-4.5) V22(8.5,-4.5) V23(9.5,-4.5) V24(10.5,-4.5) V25(11.5,-4.5) V26(12.5,-4.5) W1(-12.5,-5.5) W2(-11.5,-5.5) W3(-10.5,-5.5) W4(-9.5,-5.5) W5(-8.5,-5.5) W6(-7.5,-5.5) W7(-6.5,-5.5) W8(-5.5,-5.5) W9(-4.5,-5.5) W10(-3.5,-5.5) W11(-2.5,-5.5) W12(-1.5,-5.5) W13(-0.5,-5.5) W14(0.5,-5.5) W15(1.5,-5.5) W16(2.5,-5.5) W17(3.5,-5.5) W18(4.5,-5.5) W19(5.5,-5.5) W20(6.5,-5.5) W21(7.5,-5.5) W22(8.5,-5.5) W23(9.5,-5.5) W24(10.5,-5.5) W25(11.5,-5.5) W26(12.5,-5.5) Y1(-12.5,-6.5) Y2(-11.5,-6.5) Y3(-10.5,-6.5) Y4(-9.5,-6.5) Y5(-8.5,-6.5) Y6(-7.5,-6.5) Y7(-6.5,-6.5) Y8(-5.5,-6.5) Y9(-4.5,-6.5) Y10(-3.5,-6.5) Y11(-2.5,-6.5) Y12(-1.5,-6.5) Y13(-0.5,-6.5) Y14(0.5,-6.5) Y15(1.5,-6.5) Y16(2.5,-6.5) Y17(3.5,-6.5) Y18(4.5,-6.5) Y19(5.5,-6.5) Y20(6.5,-6.5) Y21(7.5,-6.5) Y22(8.5,-6.5) Y23(9.5,-6.5) Y24(10.5,-6.5) Y25(11.5,-6.5) Y26(12.5,-6.5)
Top Overlay:
  circle w0.25: c-14.15,12.5 r0.125
  lines w0.2: -13.5,-12.5 -13.5,13.5 12.5,13.5 13.5,12.5 13.5,-12.5 12.5,-13.5 -12.5,-13.5 -13.5,-12.5

## BGA27X27-B676/X.4 [mm]
pads (676):
  round 0.4 smd: A1(-12.5,12.5) A2(-11.5,12.5) A3(-10.5,12.5) A4(-9.5,12.5) A5(-8.5,12.5) A6(-7.5,12.5) A7(-6.5,12.5) A8(-5.5,12.5) A9(-4.5,12.5) A10(-3.5,12.5) A11(-2.5,12.5) A12(-1.5,12.5) A13(-0.5,12.5) A14(0.5,12.5) A15(1.5,12.5) A16(2.5,12.5) A17(3.5,12.5) A18(4.5,12.5) A19(5.5,12.5) A20(6.5,12.5) A21(7.5,12.5) A22(8.5,12.5) A23(9.5,12.5) A24(10.5,12.5) A25(11.5,12.5) A26(12.5,12.5) AA1(-12.5,-7.5) AA2(-11.5,-7.5) AA3(-10.5,-7.5) AA4(-9.5,-7.5) AA5(-8.5,-7.5) AA6(-7.5,-7.5) AA7(-6.5,-7.5) AA8(-5.5,-7.5) AA9(-4.5,-7.5) AA10(-3.5,-7.5) AA11(-2.5,-7.5) AA12(-1.5,-7.5) AA13(-0.5,-7.5) AA14(0.5,-7.5) AA15(1.5,-7.5) AA16(2.5,-7.5) AA17(3.5,-7.5) AA18(4.5,-7.5) AA19(5.5,-7.5) AA20(6.5,-7.5) AA21(7.5,-7.5) AA22(8.5,-7.5) AA23(9.5,-7.5) AA24(10.5,-7.5) AA25(11.5,-7.5) AA26(12.5,-7.5) AB1(-12.5,-8.5) AB2(-11.5,-8.5) AB3(-10.5,-8.5) AB4(-9.5,-8.5) AB5(-8.5,-8.5) AB6(-7.5,-8.5) AB7(-6.5,-8.5) AB8(-5.5,-8.5) AB9(-4.5,-8.5) AB10(-3.5,-8.5) AB11(-2.5,-8.5) AB12(-1.5,-8.5) AB13(-0.5,-8.5) AB14(0.5,-8.5) AB15(1.5,-8.5) AB16(2.5,-8.5) AB17(3.5,-8.5) AB18(4.5,-8.5) AB19(5.5,-8.5) AB20(6.5,-8.5) AB21(7.5,-8.5) AB22(8.5,-8.5) AB23(9.5,-8.5) AB24(10.5,-8.5) AB25(11.5,-8.5) AB26(12.5,-8.5) AC1(-12.5,-9.5) AC2(-11.5,-9.5) AC3(-10.5,-9.5) AC4(-9.5,-9.5) AC5(-8.5,-9.5) AC6(-7.5,-9.5) AC7(-6.5,-9.5) AC8(-5.5,-9.5) AC9(-4.5,-9.5) AC10(-3.5,-9.5) AC11(-2.5,-9.5) AC12(-1.5,-9.5) AC13(-0.5,-9.5) AC14(0.5,-9.5) AC15(1.5,-9.5) AC16(2.5,-9.5) AC17(3.5,-9.5) AC18(4.5,-9.5) AC19(5.5,-9.5) AC20(6.5,-9.5) AC21(7.5,-9.5) AC22(8.5,-9.5) AC23(9.5,-9.5) AC24(10.5,-9.5) AC25(11.5,-9.5) AC26(12.5,-9.5) AD1(-12.5,-10.5) AD2(-11.5,-10.5) AD3(-10.5,-10.5) AD4(-9.5,-10.5) AD5(-8.5,-10.5) AD6(-7.5,-10.5) AD7(-6.5,-10.5) AD8(-5.5,-10.5) AD9(-4.5,-10.5) AD10(-3.5,-10.5) AD11(-2.5,-10.5) AD12(-1.5,-10.5) AD13(-0.5,-10.5) AD14(0.5,-10.5) AD15(1.5,-10.5) AD16(2.5,-10.5) AD17(3.5,-10.5) AD18(4.5,-10.5) AD19(5.5,-10.5) AD20(6.5,-10.5) AD21(7.5,-10.5) AD22(8.5,-10.5) AD23(9.5,-10.5) AD24(10.5,-10.5) AD25(11.5,-10.5) AD26(12.5,-10.5) AE1(-12.5,-11.5) AE2(-11.5,-11.5) AE3(-10.5,-11.5) AE4(-9.5,-11.5) AE5(-8.5,-11.5) AE6(-7.5,-11.5) AE7(-6.5,-11.5) AE8(-5.5,-11.5) AE9(-4.5,-11.5) AE10(-3.5,-11.5) AE11(-2.5,-11.5) AE12(-1.5,-11.5) AE13(-0.5,-11.5) AE14(0.5,-11.5) AE15(1.5,-11.5) AE16(2.5,-11.5) AE17(3.5,-11.5) AE18(4.5,-11.5) AE19(5.5,-11.5) AE20(6.5,-11.5) AE21(7.5,-11.5) AE22(8.5,-11.5) AE23(9.5,-11.5) AE24(10.5,-11.5) AE25(11.5,-11.5) AE26(12.5,-11.5) AF1(-12.5,-12.5) AF2(-11.5,-12.5) AF3(-10.5,-12.5) AF4(-9.5,-12.5) AF5(-8.5,-12.5) AF6(-7.5,-12.5) AF7(-6.5,-12.5) AF8(-5.5,-12.5) AF9(-4.5,-12.5) AF10(-3.5,-12.5) AF11(-2.5,-12.5) AF12(-1.5,-12.5) AF13(-0.5,-12.5) AF14(0.5,-12.5) AF15(1.5,-12.5) AF16(2.5,-12.5) AF17(3.5,-12.5) AF18(4.5,-12.5) AF19(5.5,-12.5) AF20(6.5,-12.5) AF21(7.5,-12.5) AF22(8.5,-12.5) AF23(9.5,-12.5) AF24(10.5,-12.5) AF25(11.5,-12.5) AF26(12.5,-12.5) B1(-12.5,11.5) B2(-11.5,11.5) B3(-10.5,11.5) B4(-9.5,11.5) B5(-8.5,11.5) B6(-7.5,11.5) B7(-6.5,11.5) B8(-5.5,11.5) B9(-4.5,11.5) B10(-3.5,11.5) B11(-2.5,11.5) B12(-1.5,11.5) B13(-0.5,11.5) B14(0.5,11.5) B15(1.5,11.5) B16(2.5,11.5) B17(3.5,11.5) B18(4.5,11.5) B19(5.5,11.5) B20(6.5,11.5) B21(7.5,11.5) B22(8.5,11.5) B23(9.5,11.5) B24(10.5,11.5) B25(11.5,11.5) B26(12.5,11.5) C1(-12.5,10.5) C2(-11.5,10.5) C3(-10.5,10.5) C4(-9.5,10.5) C5(-8.5,10.5) C6(-7.5,10.5) C7(-6.5,10.5) C8(-5.5,10.5) C9(-4.5,10.5) C10(-3.5,10.5) C11(-2.5,10.5) C12(-1.5,10.5) C13(-0.5,10.5) C14(0.5,10.5) C15(1.5,10.5) C16(2.5,10.5) C17(3.5,10.5) C18(4.5,10.5) C19(5.5,10.5) C20(6.5,10.5) C21(7.5,10.5) C22(8.5,10.5) C23(9.5,10.5) C24(10.5,10.5) C25(11.5,10.5) C26(12.5,10.5) D1(-12.5,9.5) D2(-11.5,9.5) D3(-10.5,9.5) D4(-9.5,9.5) D5(-8.5,9.5) D6(-7.5,9.5) D7(-6.5,9.5) D8(-5.5,9.5) D9(-4.5,9.5) D10(-3.5,9.5) D11(-2.5,9.5) D12(-1.5,9.5) D13(-0.5,9.5) D14(0.5,9.5) D15(1.5,9.5) D16(2.5,9.5) D17(3.5,9.5) D18(4.5,9.5) D19(5.5,9.5) D20(6.5,9.5) D21(7.5,9.5) D22(8.5,9.5) D23(9.5,9.5) D24(10.5,9.5) D25(11.5,9.5) D26(12.5,9.5) E1(-12.5,8.5) E2(-11.5,8.5) E3(-10.5,8.5) E4(-9.5,8.5) E5(-8.5,8.5) E6(-7.5,8.5) E7(-6.5,8.5) E8(-5.5,8.5) E9(-4.5,8.5) E10(-3.5,8.5) E11(-2.5,8.5) E12(-1.5,8.5) E13(-0.5,8.5) E14(0.5,8.5) E15(1.5,8.5) E16(2.5,8.5) E17(3.5,8.5) E18(4.5,8.5) E19(5.5,8.5) E20(6.5,8.5) E21(7.5,8.5) E22(8.5,8.5) E23(9.5,8.5) E24(10.5,8.5) E25(11.5,8.5) E26(12.5,8.5) F1(-12.5,7.5) F2(-11.5,7.5) F3(-10.5,7.5) F4(-9.5,7.5) F5(-8.5,7.5) F6(-7.5,7.5) F7(-6.5,7.5) F8(-5.5,7.5) F9(-4.5,7.5) F10(-3.5,7.5) F11(-2.5,7.5) F12(-1.5,7.5) F13(-0.5,7.5) F14(0.5,7.5) F15(1.5,7.5) F16(2.5,7.5) F17(3.5,7.5) F18(4.5,7.5) F19(5.5,7.5) F20(6.5,7.5) F21(7.5,7.5) F22(8.5,7.5) F23(9.5,7.5) F24(10.5,7.5) F25(11.5,7.5) F26(12.5,7.5) G1(-12.5,6.5) G2(-11.5,6.5) G3(-10.5,6.5) G4(-9.5,6.5) G5(-8.5,6.5) G6(-7.5,6.5) G7(-6.5,6.5) G8(-5.5,6.5) G9(-4.5,6.5) G10(-3.5,6.5) G11(-2.5,6.5) G12(-1.5,6.5) G13(-0.5,6.5) G14(0.5,6.5) G15(1.5,6.5) G16(2.5,6.5) G17(3.5,6.5) G18(4.5,6.5) G19(5.5,6.5) G20(6.5,6.5) G21(7.5,6.5) G22(8.5,6.5) G23(9.5,6.5) G24(10.5,6.5) G25(11.5,6.5) G26(12.5,6.5) H1(-12.5,5.5) H2(-11.5,5.5) H3(-10.5,5.5) H4(-9.5,5.5) H5(-8.5,5.5) H6(-7.5,5.5) H7(-6.5,5.5) H8(-5.5,5.5) H9(-4.5,5.5) H10(-3.5,5.5) H11(-2.5,5.5) H12(-1.5,5.5) H13(-0.5,5.5) H14(0.5,5.5) H15(1.5,5.5) H16(2.5,5.5) H17(3.5,5.5) H18(4.5,5.5) H19(5.5,5.5) H20(6.5,5.5) H21(7.5,5.5) H22(8.5,5.5) H23(9.5,5.5) H24(10.5,5.5) H25(11.5,5.5) H26(12.5,5.5) J1(-12.5,4.5) J2(-11.5,4.5) J3(-10.5,4.5) J4(-9.5,4.5) J5(-8.5,4.5) J6(-7.5,4.5) J7(-6.5,4.5) J8(-5.5,4.5) J9(-4.5,4.5) J10(-3.5,4.5) J11(-2.5,4.5) J12(-1.5,4.5) J13(-0.5,4.5) J14(0.5,4.5) J15(1.5,4.5) J16(2.5,4.5) J17(3.5,4.5) J18(4.5,4.5) J19(5.5,4.5) J20(6.5,4.5) J21(7.5,4.5) J22(8.5,4.5) J23(9.5,4.5) J24(10.5,4.5) J25(11.5,4.5) J26(12.5,4.5) K1(-12.5,3.5) K2(-11.5,3.5) K3(-10.5,3.5) K4(-9.5,3.5) K5(-8.5,3.5) K6(-7.5,3.5) K7(-6.5,3.5) K8(-5.5,3.5) K9(-4.5,3.5) K10(-3.5,3.5) K11(-2.5,3.5) K12(-1.5,3.5) K13(-0.5,3.5) K14(0.5,3.5) K15(1.5,3.5) K16(2.5,3.5) K17(3.5,3.5) K18(4.5,3.5) K19(5.5,3.5) K20(6.5,3.5) K21(7.5,3.5) K22(8.5,3.5) K23(9.5,3.5) K24(10.5,3.5) K25(11.5,3.5) K26(12.5,3.5) L1(-12.5,2.5) L2(-11.5,2.5) L3(-10.5,2.5) L4(-9.5,2.5) L5(-8.5,2.5) L6(-7.5,2.5) L7(-6.5,2.5) L8(-5.5,2.5) L9(-4.5,2.5) L10(-3.5,2.5) L11(-2.5,2.5) L12(-1.5,2.5) L13(-0.5,2.5) L14(0.5,2.5) L15(1.5,2.5) L16(2.5,2.5) L17(3.5,2.5) L18(4.5,2.5) L19(5.5,2.5) L20(6.5,2.5) L21(7.5,2.5) L22(8.5,2.5) L23(9.5,2.5) L24(10.5,2.5) L25(11.5,2.5) L26(12.5,2.5) M1(-12.5,1.5) M2(-11.5,1.5) M3(-10.5,1.5) M4(-9.5,1.5) M5(-8.5,1.5) M6(-7.5,1.5) M7(-6.5,1.5) M8(-5.5,1.5) M9(-4.5,1.5) M10(-3.5,1.5) M11(-2.5,1.5) M12(-1.5,1.5) M13(-0.5,1.5) M14(0.5,1.5) M15(1.5,1.5) M16(2.5,1.5) M17(3.5,1.5) M18(4.5,1.5) M19(5.5,1.5) M20(6.5,1.5) M21(7.5,1.5) M22(8.5,1.5) M23(9.5,1.5) M24(10.5,1.5) M25(11.5,1.5) M26(12.5,1.5) N1(-12.5,0.5) N2(-11.5,0.5) N3(-10.5,0.5) N4(-9.5,0.5) N5(-8.5,0.5) N6(-7.5,0.5) N7(-6.5,0.5) N8(-5.5,0.5) N9(-4.5,0.5) N10(-3.5,0.5) N11(-2.5,0.5) N12(-1.5,0.5) N13(-0.5,0.5) N14(0.5,0.5) N15(1.5,0.5) N16(2.5,0.5) N17(3.5,0.5) N18(4.5,0.5) N19(5.5,0.5) N20(6.5,0.5) N21(7.5,0.5) N22(8.5,0.5) N23(9.5,0.5) N24(10.5,0.5) N25(11.5,0.5) N26(12.5,0.5) P1(-12.5,-0.5) P2(-11.5,-0.5) P3(-10.5,-0.5) P4(-9.5,-0.5) P5(-8.5,-0.5) P6(-7.5,-0.5) P7(-6.5,-0.5) P8(-5.5,-0.5) P9(-4.5,-0.5) P10(-3.5,-0.5) P11(-2.5,-0.5) P12(-1.5,-0.5) P13(-0.5,-0.5) P14(0.5,-0.5) P15(1.5,-0.5) P16(2.5,-0.5) P17(3.5,-0.5) P18(4.5,-0.5) P19(5.5,-0.5) P20(6.5,-0.5) P21(7.5,-0.5) P22(8.5,-0.5) P23(9.5,-0.5) P24(10.5,-0.5) P25(11.5,-0.5) P26(12.5,-0.5) R1(-12.5,-1.5) R2(-11.5,-1.5) R3(-10.5,-1.5) R4(-9.5,-1.5) R5(-8.5,-1.5) R6(-7.5,-1.5) R7(-6.5,-1.5) R8(-5.5,-1.5) R9(-4.5,-1.5) R10(-3.5,-1.5) R11(-2.5,-1.5) R12(-1.5,-1.5) R13(-0.5,-1.5) R14(0.5,-1.5) R15(1.5,-1.5) R16(2.5,-1.5) R17(3.5,-1.5) R18(4.5,-1.5) R19(5.5,-1.5) R20(6.5,-1.5) R21(7.5,-1.5) R22(8.5,-1.5) R23(9.5,-1.5) R24(10.5,-1.5) R25(11.5,-1.5) R26(12.5,-1.5) T1(-12.5,-2.5) T2(-11.5,-2.5) T3(-10.5,-2.5) T4(-9.5,-2.5) T5(-8.5,-2.5) T6(-7.5,-2.5) T7(-6.5,-2.5) T8(-5.5,-2.5) T9(-4.5,-2.5) T10(-3.5,-2.5) T11(-2.5,-2.5) T12(-1.5,-2.5) T13(-0.5,-2.5) T14(0.5,-2.5) T15(1.5,-2.5) T16(2.5,-2.5) T17(3.5,-2.5) T18(4.5,-2.5) T19(5.5,-2.5) T20(6.5,-2.5) T21(7.5,-2.5) T22(8.5,-2.5) T23(9.5,-2.5) T24(10.5,-2.5) T25(11.5,-2.5) T26(12.5,-2.5) U1(-12.5,-3.5) U2(-11.5,-3.5) U3(-10.5,-3.5) U4(-9.5,-3.5) U5(-8.5,-3.5) U6(-7.5,-3.5) U7(-6.5,-3.5) U8(-5.5,-3.5) U9(-4.5,-3.5) U10(-3.5,-3.5) U11(-2.5,-3.5) U12(-1.5,-3.5) U13(-0.5,-3.5) U14(0.5,-3.5) U15(1.5,-3.5) U16(2.5,-3.5) U17(3.5,-3.5) U18(4.5,-3.5) U19(5.5,-3.5) U20(6.5,-3.5) U21(7.5,-3.5) U22(8.5,-3.5) U23(9.5,-3.5) U24(10.5,-3.5) U25(11.5,-3.5) U26(12.5,-3.5) V1(-12.5,-4.5) V2(-11.5,-4.5) V3(-10.5,-4.5) V4(-9.5,-4.5) V5(-8.5,-4.5) V6(-7.5,-4.5) V7(-6.5,-4.5) V8(-5.5,-4.5) V9(-4.5,-4.5) V10(-3.5,-4.5) V11(-2.5,-4.5) V12(-1.5,-4.5) V13(-0.5,-4.5) V14(0.5,-4.5) V15(1.5,-4.5) V16(2.5,-4.5) V17(3.5,-4.5) V18(4.5,-4.5) V19(5.5,-4.5) V20(6.5,-4.5) V21(7.5,-4.5) V22(8.5,-4.5) V23(9.5,-4.5) V24(10.5,-4.5) V25(11.5,-4.5) V26(12.5,-4.5) W1(-12.5,-5.5) W2(-11.5,-5.5) W3(-10.5,-5.5) W4(-9.5,-5.5) W5(-8.5,-5.5) W6(-7.5,-5.5) W7(-6.5,-5.5) W8(-5.5,-5.5) W9(-4.5,-5.5) W10(-3.5,-5.5) W11(-2.5,-5.5) W12(-1.5,-5.5) W13(-0.5,-5.5) W14(0.5,-5.5) W15(1.5,-5.5) W16(2.5,-5.5) W17(3.5,-5.5) W18(4.5,-5.5) W19(5.5,-5.5) W20(6.5,-5.5) W21(7.5,-5.5) W22(8.5,-5.5) W23(9.5,-5.5) W24(10.5,-5.5) W25(11.5,-5.5) W26(12.5,-5.5) Y1(-12.5,-6.5) Y2(-11.5,-6.5) Y3(-10.5,-6.5) Y4(-9.5,-6.5) Y5(-8.5,-6.5) Y6(-7.5,-6.5) Y7(-6.5,-6.5) Y8(-5.5,-6.5) Y9(-4.5,-6.5) Y10(-3.5,-6.5) Y11(-2.5,-6.5) Y12(-1.5,-6.5) Y13(-0.5,-6.5) Y14(0.5,-6.5) Y15(1.5,-6.5) Y16(2.5,-6.5) Y17(3.5,-6.5) Y18(4.5,-6.5) Y19(5.5,-6.5) Y20(6.5,-6.5) Y21(7.5,-6.5) Y22(8.5,-6.5) Y23(9.5,-6.5) Y24(10.5,-6.5) Y25(11.5,-6.5) Y26(12.5,-6.5)
Top Overlay:
  circle w0.25: c-14.15,12.5 r0.125
  lines w0.2: -13.5,-12.5 -12.5,-13.5 12.5,-13.5 13.5,-12.5 13.5,12.5 12.5,13.5 -13.5,13.5 -13.5,-12.5

## BGA29X29-B729 [mm]
pads (729):
  round 0.5 smd: A1(-13,13) A2(-12,13) A3(-11,13) A4(-10,13) A5(-9,13) A6(-8,13) A7(-7,13) A8(-6,13) A9(-5,13) A10(-4,13) A11(-3,13) A12(-2,13) A13(-1,13) A14(0,13) A15(1,13) A16(2,13) A17(3,13) A18(4,13) A19(5,13) A20(6,13) A21(7,13) A22(8,13) A23(9,13) A24(10,13) A25(11,13) A26(12,13) A27(13,13) AA1(-13,-7) AA2(-12,-7) AA3(-11,-7) AA4(-10,-7) AA5(-9,-7) AA6(-8,-7) AA7(-7,-7) AA8(-6,-7) AA9(-5,-7) AA10(-4,-7) AA11(-3,-7) AA12(-2,-7) AA13(-1,-7) AA14(0,-7) AA15(1,-7) AA16(2,-7) AA17(3,-7) AA18(4,-7) AA19(5,-7) AA20(6,-7) AA21(7,-7) AA22(8,-7) AA23(9,-7) AA24(10,-7) AA25(11,-7) AA26(12,-7) AA27(13,-7) AB1(-13,-8) AB2(-12,-8) AB3(-11,-8) AB4(-10,-8) AB5(-9,-8) AB6(-8,-8) AB7(-7,-8) AB8(-6,-8) AB9(-5,-8) AB10(-4,-8) AB11(-3,-8) AB12(-2,-8) AB13(-1,-8) AB14(0,-8) AB15(1,-8) AB16(2,-8) AB17(3,-8) AB18(4,-8) AB19(5,-8) AB20(6,-8) AB21(7,-8) AB22(8,-8) AB23(9,-8) AB24(10,-8) AB25(11,-8) AB26(12,-8) AB27(13,-8) AC1(-13,-9) AC2(-12,-9) AC3(-11,-9) AC4(-10,-9) AC5(-9,-9) AC6(-8,-9) AC7(-7,-9) AC8(-6,-9) AC9(-5,-9) AC10(-4,-9) AC11(-3,-9) AC12(-2,-9) AC13(-1,-9) AC14(0,-9) AC15(1,-9) AC16(2,-9) AC17(3,-9) AC18(4,-9) AC19(5,-9) AC20(6,-9) AC21(7,-9) AC22(8,-9) AC23(9,-9) AC24(10,-9) AC25(11,-9) AC26(12,-9) AC27(13,-9) AD1(-13,-10) AD2(-12,-10) AD3(-11,-10) AD4(-10,-10) AD5(-9,-10) AD6(-8,-10) AD7(-7,-10) AD8(-6,-10) AD9(-5,-10) AD10(-4,-10) AD11(-3,-10) AD12(-2,-10) AD13(-1,-10) AD14(0,-10) AD15(1,-10) AD16(2,-10) AD17(3,-10) AD18(4,-10) AD19(5,-10) AD20(6,-10) AD21(7,-10) AD22(8,-10) AD23(9,-10) AD24(10,-10) AD25(11,-10) AD26(12,-10) AD27(13,-10) AE1(-13,-11) AE2(-12,-11) AE3(-11,-11) AE4(-10,-11) AE5(-9,-11) AE6(-8,-11) AE7(-7,-11) AE8(-6,-11) AE9(-5,-11) AE10(-4,-11) AE11(-3,-11) AE12(-2,-11) AE13(-1,-11) AE14(0,-11) AE15(1,-11) AE16(2,-11) AE17(3,-11) AE18(4,-11) AE19(5,-11) AE20(6,-11) AE21(7,-11) AE22(8,-11) AE23(9,-11) AE24(10,-11) AE25(11,-11) AE26(12,-11) AE27(13,-11) AF1(-13,-12) AF2(-12,-12) AF3(-11,-12) AF4(-10,-12) AF5(-9,-12) AF6(-8,-12) AF7(-7,-12) AF8(-6,-12) AF9(-5,-12) AF10(-4,-12) AF11(-3,-12) AF12(-2,-12) AF13(-1,-12) AF14(0,-12) AF15(1,-12) AF16(2,-12) AF17(3,-12) AF18(4,-12) AF19(5,-12) AF20(6,-12) AF21(7,-12) AF22(8,-12) AF23(9,-12) AF24(10,-12) AF25(11,-12) AF26(12,-12) AF27(13,-12) AG1(-13,-13) AG2(-12,-13) AG3(-11,-13) AG4(-10,-13) AG5(-9,-13) AG6(-8,-13) AG7(-7,-13) AG8(-6,-13) AG9(-5,-13) AG10(-4,-13) AG11(-3,-13) AG12(-2,-13) AG13(-1,-13) AG14(0,-13) AG15(1,-13) AG16(2,-13) AG17(3,-13) AG18(4,-13) AG19(5,-13) AG20(6,-13) AG21(7,-13) AG22(8,-13) AG23(9,-13) AG24(10,-13) AG25(11,-13) AG26(12,-13) AG27(13,-13) B1(-13,12) B2(-12,12) B3(-11,12) B4(-10,12) B5(-9,12) B6(-8,12) B7(-7,12) B8(-6,12) B9(-5,12) B10(-4,12) B11(-3,12) B12(-2,12) B13(-1,12) B14(0,12) B15(1,12) B16(2,12) B17(3,12) B18(4,12) B19(5,12) B20(6,12) B21(7,12) B22(8,12) B23(9,12) B24(10,12) B25(11,12) B26(12,12) B27(13,12) C1(-13,11) C2(-12,11) C3(-11,11) C4(-10,11) C5(-9,11) C6(-8,11) C7(-7,11) C8(-6,11) C9(-5,11) C10(-4,11) C11(-3,11) C12(-2,11) C13(-1,11) C14(0,11) C15(1,11) C16(2,11) C17(3,11) C18(4,11) C19(5,11) C20(6,11) C21(7,11) C22(8,11) C23(9,11) C24(10,11) C25(11,11) C26(12,11) C27(13,11) D1(-13,10) D2(-12,10) D3(-11,10) D4(-10,10) D5(-9,10) D6(-8,10) D7(-7,10) D8(-6,10) D9(-5,10) D10(-4,10) D11(-3,10) D12(-2,10) D13(-1,10) D14(0,10) D15(1,10) D16(2,10) D17(3,10) D18(4,10) D19(5,10) D20(6,10) D21(7,10) D22(8,10) D23(9,10) D24(10,10) D25(11,10) D26(12,10) D27(13,10) E1(-13,9) E2(-12,9) E3(-11,9) E4(-10,9) E5(-9,9) E6(-8,9) E7(-7,9) E8(-6,9) E9(-5,9) E10(-4,9) E11(-3,9) E12(-2,9) E13(-1,9) E14(0,9) E15(1,9) E16(2,9) E17(3,9) E18(4,9) E19(5,9) E20(6,9) E21(7,9) E22(8,9) E23(9,9) E24(10,9) E25(11,9) E26(12,9) E27(13,9) F1(-13,8) F2(-12,8) F3(-11,8) F4(-10,8) F5(-9,8) F6(-8,8) F7(-7,8) F8(-6,8) F9(-5,8) F10(-4,8) F11(-3,8) F12(-2,8) F13(-1,8) F14(0,8) F15(1,8) F16(2,8) F17(3,8) F18(4,8) F19(5,8) F20(6,8) F21(7,8) F22(8,8) F23(9,8) F24(10,8) F25(11,8) F26(12,8) F27(13,8) G1(-13,7) G2(-12,7) G3(-11,7) G4(-10,7) G5(-9,7) G6(-8,7) G7(-7,7) G8(-6,7) G9(-5,7) G10(-4,7) G11(-3,7) G12(-2,7) G13(-1,7) G14(0,7) G15(1,7) G16(2,7) G17(3,7) G18(4,7) G19(5,7) G20(6,7) G21(7,7) G22(8,7) G23(9,7) G24(10,7) G25(11,7) G26(12,7) G27(13,7) H1(-13,6) H2(-12,6) H3(-11,6) H4(-10,6) H5(-9,6) H6(-8,6) H7(-7,6) H8(-6,6) H9(-5,6) H10(-4,6) H11(-3,6) H12(-2,6) H13(-1,6) H14(0,6) H15(1,6) H16(2,6) H17(3,6) H18(4,6) H19(5,6) H20(6,6) H21(7,6) H22(8,6) H23(9,6) H24(10,6) H25(11,6) H26(12,6) H27(13,6) J1(-13,5) J2(-12,5) J3(-11,5) J4(-10,5) J5(-9,5) J6(-8,5) J7(-7,5) J8(-6,5) J9(-5,5) J10(-4,5) J11(-3,5) J12(-2,5) J13(-1,5) J14(0,5) J15(1,5) J16(2,5) J17(3,5) J18(4,5) J19(5,5) J20(6,5) J21(7,5) J22(8,5) J23(9,5) J24(10,5) J25(11,5) J26(12,5) J27(13,5) K1(-13,4) K2(-12,4) K3(-11,4) K4(-10,4) K5(-9,4) K6(-8,4) K7(-7,4) K8(-6,4) K9(-5,4) K10(-4,4) K11(-3,4) K12(-2,4) K13(-1,4) K14(0,4) K15(1,4) K16(2,4) K17(3,4) K18(4,4) K19(5,4) K20(6,4) K21(7,4) K22(8,4) K23(9,4) K24(10,4) K25(11,4) K26(12,4) K27(13,4) L1(-13,3) L2(-12,3) L3(-11,3) L4(-10,3) L5(-9,3) L6(-8,3) L7(-7,3) L8(-6,3) L9(-5,3) L10(-4,3) L11(-3,3) L12(-2,3) L13(-1,3) L14(0,3) L15(1,3) L16(2,3) L17(3,3) L18(4,3) L19(5,3) L20(6,3) L21(7,3) L22(8,3) L23(9,3) L24(10,3) L25(11,3) L26(12,3) L27(13,3) M1(-13,2) M2(-12,2) M3(-11,2) M4(-10,2) M5(-9,2) M6(-8,2) M7(-7,2) M8(-6,2) M9(-5,2) M10(-4,2) M11(-3,2) M12(-2,2) M13(-1,2) M14(0,2) M15(1,2) M16(2,2) M17(3,2) M18(4,2) M19(5,2) M20(6,2) M21(7,2) M22(8,2) M23(9,2) M24(10,2) M25(11,2) M26(12,2) M27(13,2) N1(-13,1) N2(-12,1) N3(-11,1) N4(-10,1) N5(-9,1) N6(-8,1) N7(-7,1) N8(-6,1) N9(-5,1) N10(-4,1) N11(-3,1) N12(-2,1) N13(-1,1) N14(0,1) N15(1,1) N16(2,1) N17(3,1) N18(4,1) N19(5,1) N20(6,1) N21(7,1) N22(8,1) N23(9,1) N24(10,1) N25(11,1) N26(12,1) N27(13,1) P1(-13,0) P2(-12,0) P3(-11,0) P4(-10,0) P5(-9,0) P6(-8,0) P7(-7,0) P8(-6,0) P9(-5,0) P10(-4,0) P11(-3,0) P12(-2,0) P13(-1,0) P14(0,0) P15(1,0) P16(2,0) P17(3,0) P18(4,0) P19(5,0) P20(6,0) P21(7,0) P22(8,0) P23(9,0) P24(10,0) P25(11,0) P26(12,0) P27(13,0) R1(-13,-1) R2(-12,-1) R3(-11,-1) R4(-10,-1) R5(-9,-1) R6(-8,-1) R7(-7,-1) R8(-6,-1) R9(-5,-1) R10(-4,-1) R11(-3,-1) R12(-2,-1) R13(-1,-1) R14(0,-1) R15(1,-1) R16(2,-1) R17(3,-1) R18(4,-1) R19(5,-1) R20(6,-1) R21(7,-1) R22(8,-1) R23(9,-1) R24(10,-1) R25(11,-1) R26(12,-1) R27(13,-1) T1(-13,-2) T2(-12,-2) T3(-11,-2) T4(-10,-2) T5(-9,-2) T6(-8,-2) T7(-7,-2) T8(-6,-2) T9(-5,-2) T10(-4,-2) T11(-3,-2) T12(-2,-2) T13(-1,-2) T14(0,-2) T15(1,-2) T16(2,-2) T17(3,-2) T18(4,-2) T19(5,-2) T20(6,-2) T21(7,-2) T22(8,-2) T23(9,-2) T24(10,-2) T25(11,-2) T26(12,-2) T27(13,-2) U1(-13,-3) U2(-12,-3) U3(-11,-3) U4(-10,-3) U5(-9,-3) U6(-8,-3) U7(-7,-3) U8(-6,-3) U9(-5,-3) U10(-4,-3) U11(-3,-3) U12(-2,-3) U13(-1,-3) U14(0,-3) U15(1,-3) U16(2,-3) U17(3,-3) U18(4,-3) U19(5,-3) U20(6,-3) U21(7,-3) U22(8,-3) U23(9,-3) U24(10,-3) U25(11,-3) U26(12,-3) U27(13,-3) V1(-13,-4) V2(-12,-4) V3(-11,-4) V4(-10,-4) V5(-9,-4) V6(-8,-4) V7(-7,-4) V8(-6,-4) V9(-5,-4) V10(-4,-4) V11(-3,-4) V12(-2,-4) V13(-1,-4) V14(0,-4) V15(1,-4) V16(2,-4) V17(3,-4) V18(4,-4) V19(5,-4) V20(6,-4) V21(7,-4) V22(8,-4) V23(9,-4) V24(10,-4) V25(11,-4) V26(12,-4) V27(13,-4) W1(-13,-5) W2(-12,-5) W3(-11,-5) W4(-10,-5) W5(-9,-5) W6(-8,-5) W7(-7,-5) W8(-6,-5) W9(-5,-5) W10(-4,-5) W11(-3,-5) W12(-2,-5) W13(-1,-5) W14(0,-5) W15(1,-5) W16(2,-5) W17(3,-5) W18(4,-5) W19(5,-5) W20(6,-5) W21(7,-5) W22(8,-5) W23(9,-5) W24(10,-5) W25(11,-5) W26(12,-5) W27(13,-5) Y1(-13,-6) Y2(-12,-6) Y3(-11,-6) Y4(-10,-6) Y5(-9,-6) Y6(-8,-6) Y7(-7,-6) Y8(-6,-6) Y9(-5,-6) Y10(-4,-6) Y11(-3,-6) Y12(-2,-6) Y13(-1,-6) Y14(0,-6) Y15(1,-6) Y16(2,-6) Y17(3,-6) Y18(4,-6) Y19(5,-6) Y20(6,-6) Y21(7,-6) Y22(8,-6) Y23(9,-6) Y24(10,-6) Y25(11,-6) Y26(12,-6) Y27(13,-6)
Top Overlay:
  circle w0.25: c-15.155,13 r0.125
  lines w0.2: -14.5,-13.5 -13.5,-14.5 13.5,-14.5 14.5,-13.5 14.5,13.5 13.5,14.5 -14.5,14.5 -14.5,-13.5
